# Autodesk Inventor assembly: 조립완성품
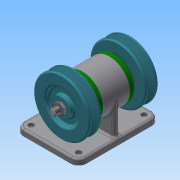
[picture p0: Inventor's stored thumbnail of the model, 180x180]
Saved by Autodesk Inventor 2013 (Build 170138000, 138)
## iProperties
Created: 2019-09
Part Number: 조립완성품
Document SubType Name: Assembly
Designer: Administrator
Author: Administrator
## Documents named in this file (10)
- C:\Users\Administrator\Desktop\490904V1020\조립완성품.iam
- C:\Users\Administrator\Desktop\490904V1020\본체.ipt
- C:\Users\Administrator\Desktop\490904V1020\V-벨트풀리.ipt
- C:\Users\Administrator\Desktop\490904V1020\너트 M10x1.ipt
- C:\Users\Administrator\Desktop\490904V1020\베어링 6004.ipt
- C:\Users\Administrator\Desktop\490904V1020\볼트 M4.ipt
- C:\Users\Administrator\Desktop\490904V1020\오일 실 17 30 5.ipt
- C:\Users\Administrator\Desktop\490904V1020\축.ipt
- C:\Users\Administrator\Desktop\490904V1020\커버.ipt
- C:\Users\Administrator\Desktop\490904V1020\키 5 x 5 x 12.ipt
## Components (2 placed, 1 different names)
1. V-벨트풀리:1
2. V-벨트풀리:2
